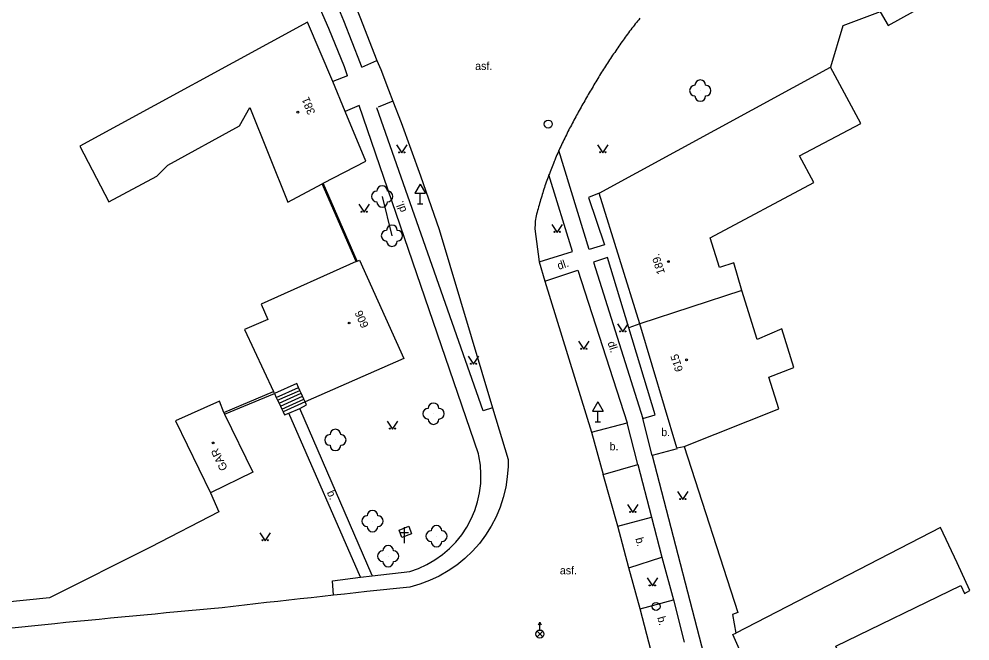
# Model space of a CAD drawing. Extents: x -536391 to -535419, y -1201788 to -1200779.
# Drawn here: x -535590.1 to -535501, y -1201602.5 to -1201544.3 of the extents above; entities that cross this region are included whole.
import ezdxf

# ---------------------------------------------------------------- set-up
doc = ezdxf.new("R2010")
doc.units = 0
for name, color, linetype in [('CIZÍ_NADZEM_POPIS', 7, 'Continuous'), ('CIZÍ_PODZEM', 7, 'Continuous'), ('CIZÍ_PODZEM_POPIS', 7, 'Continuous'), ('ELE_EON', 7, 'Continuous'), ('ELE_EON_POPIS', 7, 'Continuous'), ('KONEC_VEDENÍ', 7, 'Continuous'), ('POL_ZNAČKA_PRACOVNÍ', 7, 'Continuous'), ('SDEL_EON', 7, 'Continuous'), ('SDEL_EON_POPIS', 7, 'Continuous'), ('TECH_OCHR_PÁSMO_HRAN', 7, 'Continuous'), ('ZP_EON', 7, 'Continuous')]:
    doc.layers.add(name, color=color, linetype=linetype)

msp = doc.modelspace()

# ---------------------------------------------------------------- linework, layer by layer
at = {"layer": 'CIZÍ_PODZEM'}
for p, q in [((-535553.96, -1201593.36), (-535553.96, -1201591.86)), ((-535554.335, -1201592.36), (-535553.585, -1201592.36))]:
    msp.add_line(p, q, dxfattribs=at)
for centre in [(-535563.95, -1201552.98), (-535529.23, -1201566.99), (-535559.15, -1201572.74), (-535527.52, -1201576.19), (-535571.89, -1201583.98)]:
    msp.add_circle(centre, 0.0875, dxfattribs=at)
at = {"layer": 'CIZÍ_PODZEM_POPIS'}
for p, q in [((-535552.48, -1201559.724), (-535552.98, -1201560.59)), ((-535552.48, -1201559.724), (-535551.98, -1201560.59)), ((-535552.98, -1201560.59), (-535551.98, -1201560.59)), ((-535552.48, -1201561.59), (-535552.48, -1201560.59)), ((-535552.73, -1201561.59), (-535552.23, -1201561.59)), ((-535535.84, -1201580.134), (-535536.34, -1201581)), ((-535535.84, -1201580.134), (-535535.34, -1201581)), ((-535536.34, -1201581), (-535535.34, -1201581)), ((-535535.84, -1201582), (-535535.84, -1201581)), ((-535536.09, -1201582), (-535535.59, -1201582))]:
    msp.add_line(p, q, dxfattribs=at)
for points in [[(-535509.4, -1201543.6), (-535512.88, -1201544.9), (-535514.03, -1201548.76)], [(-535558.47, -1201566.98), (-535561.66, -1201559.7)], [(-535558.38, -1201566.94), (-535561.57, -1201559.65)], [(-535570.89, -1201581.11), (-535566.22, -1201579.17)], [(-535570.81, -1201581.28), (-535566.14, -1201579.35)], [(-535527.76, -1201584.32), (-535522.72, -1201599.86), (-535523.22, -1201600.05), (-535522.9, -1201601.79)], [(-535572.12, -1201588.65), (-535571.35, -1201590.42), (-535577.76, -1201593.75), (-535587.2, -1201598.48), (-535604.18, -1201600.22)]]:
    msp.add_lwpolyline(points, dxfattribs=at)
at = {"layer": 'ELE_EON'}
for centre, radius in [((-535540.49, -1201554.1), 0.375), ((-535540.49, -1201554.1), 0.0005), ((-535530.38, -1201599.301), 0.375), ((-535530.38, -1201599.301), 0.0005)]:
    msp.add_circle(centre, radius, dxfattribs=at)
at = {"layer": 'ELE_EON_POPIS'}
for p, q in [((-535541.27, -1201601.505), (-535541.27, -1201600.755)), ((-535541.535, -1201602.144), (-535541.006, -1201601.616)), ((-535541.006, -1201602.148), (-535541.535, -1201601.616))]:
    msp.add_line(p, q, dxfattribs=at)
msp.add_lwpolyline([(-535541.395, -1201601.005), (-535541.27, -1201600.755), (-535541.145, -1201601.005)], dxfattribs=at)
msp.add_circle((-535541.27, -1201601.88), 0.375, dxfattribs=at)
at = {"layer": 'KONEC_VEDENÍ'}
msp.add_lwpolyline([(-535556.05, -1201560.88), (-535555.13, -1201564.56)], dxfattribs=at)
for centre in [(-535526.24, -1201550.97), (-535556.05, -1201560.88), (-535555.13, -1201564.56), (-535551.23, -1201581.24), (-535560.43, -1201583.7), (-535556.95, -1201591.3), (-535550.96, -1201592.71), (-535555.48, -1201594.59)]:
    msp.add_circle(centre, 0.0005, dxfattribs=at)
for centre, start, end in [((-535526.24, -1201550.47), 0, 179.99999), ((-535526.74, -1201550.97), 89.99999, 269.99999), ((-535525.74, -1201550.97), 270, 89.99999), ((-535526.24, -1201551.47), 179.99999, 359.99999), ((-535556.05, -1201560.38), 0, 179.99999), ((-535556.55, -1201560.88), 89.99999, 269.99999), ((-535555.55, -1201560.88), 270, 89.99999), ((-535556.05, -1201561.38), 179.99999, 359.99999), ((-535555.13, -1201564.06), 0, 179.99999), ((-535555.63, -1201564.56), 89.99999, 269.99999), ((-535554.63, -1201564.56), 270, 89.99999), ((-535555.13, -1201565.06), 179.99999, 359.99999), ((-535551.73, -1201581.24), 89.99999, 269.99999), ((-535551.23, -1201580.74), 0, 179.99999), ((-535550.73, -1201581.24), 270, 89.99999), ((-535551.23, -1201581.74), 179.99999, 359.99999), ((-535560.93, -1201583.7), 89.99999, 269.99999), ((-535560.43, -1201583.2), 0, 179.99999), ((-535559.93, -1201583.7), 270, 89.99999), ((-535560.43, -1201584.2), 179.99999, 359.99999), ((-535556.95, -1201590.8), 0, 179.99999), ((-535557.45, -1201591.3), 89.99999, 269.99999), ((-535556.45, -1201591.3), 270, 89.99999), ((-535556.95, -1201591.8), 179.99999, 359.99999), ((-535551.46, -1201592.71), 89.99999, 269.99999), ((-535550.96, -1201592.21), 0, 179.99999), ((-535550.46, -1201592.71), 270, 89.99999), ((-535550.96, -1201593.21), 179.99999, 359.99999), ((-535555.98, -1201594.59), 89.99999, 269.99999), ((-535555.48, -1201594.09), 0, 179.99999), ((-535554.98, -1201594.59), 270, 89.99999), ((-535555.48, -1201595.09), 179.99999, 359.99999)]:
    msp.add_arc(centre, 0.5, start, end, dxfattribs=at)
at = {"layer": 'SDEL_EON'}
for points in [[(-535554.71, -1201556.06), (-535554.21, -1201556.81), (-535553.71, -1201556.06)], [(-535535.87, -1201556.04), (-535535.37, -1201556.79), (-535534.87, -1201556.04)], [(-535558.24, -1201561.62), (-535557.74, -1201562.37), (-535557.24, -1201561.62)], [(-535540.15, -1201563.5), (-535539.65, -1201564.25), (-535539.15, -1201563.5)], [(-535534, -1201572.83), (-535533.5, -1201573.58), (-535533, -1201572.83)], [(-535537.65, -1201574.45), (-535537.15, -1201575.2), (-535536.65, -1201574.45)], [(-535547.98, -1201575.86), (-535547.48, -1201576.61), (-535546.98, -1201575.86)], [(-535555.57, -1201581.93), (-535555.07, -1201582.68), (-535554.57, -1201581.93)], [(-535528.37, -1201588.54), (-535527.87, -1201589.29), (-535527.37, -1201588.54)], [(-535533.07, -1201589.74), (-535532.57, -1201590.49), (-535532.07, -1201589.74)], [(-535567.51, -1201592.39), (-535567.01, -1201593.14), (-535566.51, -1201592.39)], [(-535531.23, -1201596.63), (-535530.73, -1201597.38), (-535530.23, -1201596.63)]]:
    msp.add_lwpolyline(points, dxfattribs=at)
for centre in [(-535535.62, -1201556.74), (-535535.12, -1201556.74), (-535554.46, -1201556.76), (-535553.96, -1201556.76), (-535557.99, -1201562.32), (-535557.49, -1201562.32), (-535539.9, -1201564.2), (-535539.4, -1201564.2), (-535533.75, -1201573.53), (-535533.25, -1201573.53), (-535537.4, -1201575.15), (-535536.9, -1201575.15), (-535547.73, -1201576.56), (-535547.23, -1201576.56), (-535555.32, -1201582.63), (-535554.82, -1201582.63), (-535528.12, -1201589.24), (-535527.62, -1201589.24), (-535532.82, -1201590.44), (-535532.32, -1201590.44), (-535567.26, -1201593.09), (-535566.76, -1201593.09), (-535530.98, -1201597.33), (-535530.48, -1201597.33)]:
    msp.add_circle(centre, 0.05, dxfattribs=at)
at = {"layer": 'SDEL_EON_POPIS'}
for points in [[(-535561.57, -1201559.65), (-535557.59, -1201557.59), (-535559.5, -1201552.92), (-535560.67, -1201550.12), (-535563.03, -1201544.54)], [(-535535.71, -1201560.57), (-535514.03, -1201548.76)], [(-535561.66, -1201559.7), (-535561.57, -1201559.65)], [(-535531.9, -1201572.83), (-535535.71, -1201560.57)], [(-535558.38, -1201566.94), (-535558.16, -1201566.84), (-535554.01, -1201576.07), (-535563.27, -1201580.14)], [(-535558.47, -1201566.98), (-535558.38, -1201566.94)], [(-535528.44, -1201584.45), (-535531.9, -1201572.83)], [(-535563.88, -1201578.78), (-535564.05, -1201578.41), (-535566.14, -1201579.35)], [(-535563.76, -1201579.05), (-535563.88, -1201578.78)], [(-535566.14, -1201579.35), (-535566.22, -1201579.17)], [(-535563.64, -1201579.32), (-535563.76, -1201579.05)], [(-535563.51, -1201579.6), (-535563.64, -1201579.32)], [(-535563.39, -1201579.87), (-535563.51, -1201579.6)], [(-535563.27, -1201580.14), (-535563.39, -1201579.87)], [(-535570.81, -1201581.28), (-535568.17, -1201586.7), (-535572.12, -1201588.65)], [(-535570.89, -1201581.11), (-535570.81, -1201581.28)], [(-535528.44, -1201584.45), (-535527.76, -1201584.32)], [(-535523.18, -1201601.94), (-535522.9, -1201601.79)], [(-535516.38, -1201617.2), (-535521.06, -1201606.7), (-535521.43, -1201605.87), (-535523.18, -1201601.94)]]:
    msp.add_lwpolyline(points, dxfattribs=at)
at = {"layer": 'TECH_OCHR_PÁSMO_HRAN'}
for points in [[(-535559.28, -1201549.57), (-535559.59, -1201548.75), (-535561.04, -1201545.16), (-535567.24, -1201530.99), (-535567.78, -1201529.85), (-535568.21, -1201528.88), (-535572, -1201520.91), (-535578.88, -1201508.46), (-535580.82, -1201505.2), (-535588.58, -1201492.55)], [(-535566.65, -1201524.99), (-535563.37, -1201531.99), (-535558.46, -1201543.26), (-535558.14, -1201544.05), (-535556.54, -1201548.16)], [(-535557.96, -1201548.78), (-535558.09, -1201548.43), (-535559.64, -1201544.42), (-535559.94, -1201543.67), (-535565.46, -1201531.02), (-535568.06, -1201525.62)], [(-535531.89, -1201544.19), (-535532, -1201544.32), (-535532.11, -1201544.45), (-535532.22, -1201544.59), (-535532.33, -1201544.72), (-535532.43, -1201544.86), (-535532.54, -1201544.99), (-535532.65, -1201545.13), (-535532.75, -1201545.27), (-535532.86, -1201545.4), (-535532.96, -1201545.54), (-535533.06, -1201545.68), (-535533.17, -1201545.82), (-535533.27, -1201545.96), (-535533.37, -1201546.1), (-535533.47, -1201546.24), (-535533.57, -1201546.38), (-535533.67, -1201546.52), (-535533.77, -1201546.67), (-535533.87, -1201546.81), (-535533.97, -1201546.95), (-535534.07, -1201547.09), (-535534.16, -1201547.23), (-535534.26, -1201547.38), (-535534.36, -1201547.52), (-535534.45, -1201547.66), (-535534.55, -1201547.81), (-535534.65, -1201547.95), (-535534.74, -1201548.09), (-535534.84, -1201548.24), (-535534.93, -1201548.38), (-535535.02, -1201548.53), (-535535.12, -1201548.67), (-535535.21, -1201548.82), (-535535.3, -1201548.96), (-535535.39, -1201549.11), (-535535.49, -1201549.25), (-535535.58, -1201549.4), (-535535.67, -1201549.55), (-535535.76, -1201549.69)], [(-535557.96, -1201548.78), (-535556.54, -1201548.16)], [(-535556.54, -1201548.16), (-535556.17, -1201548.99), (-535555.44, -1201550.89)], [(-535559.28, -1201549.57), (-535560.67, -1201550.12)], [(-535535.76, -1201549.69), (-535535.85, -1201549.84), (-535535.94, -1201549.99), (-535536.03, -1201550.14), (-535536.12, -1201550.28), (-535536.2, -1201550.43), (-535536.29, -1201550.58), (-535536.38, -1201550.73), (-535536.47, -1201550.88), (-535536.56, -1201551.02), (-535536.64, -1201551.17), (-535536.73, -1201551.32), (-535536.82, -1201551.47), (-535536.9, -1201551.62), (-535536.99, -1201551.77), (-535537.07, -1201551.92), (-535537.16, -1201552.07), (-535537.25, -1201552.22), (-535537.33, -1201552.37), (-535537.41, -1201552.52), (-535537.5, -1201552.67), (-535537.58, -1201552.83), (-535537.67, -1201552.98), (-535537.75, -1201553.13), (-535537.83, -1201553.28), (-535537.91, -1201553.43), (-535538, -1201553.58), (-535538.08, -1201553.74), (-535538.16, -1201553.89), (-535538.24, -1201554.04), (-535538.32, -1201554.19), (-535538.4, -1201554.35), (-535538.48, -1201554.5), (-535538.56, -1201554.65), (-535538.64, -1201554.81), (-535538.71, -1201554.96), (-535538.79, -1201555.12), (-535538.87, -1201555.27), (-535538.94, -1201555.42), (-535539.02, -1201555.58), (-535539.09, -1201555.73), (-535539.17, -1201555.89), (-535539.24, -1201556.05), (-535539.31, -1201556.2), (-535539.39, -1201556.36), (-535539.46, -1201556.51), (-535539.49, -1201556.58)], [(-535555.44, -1201550.89), (-535555.04, -1201551.97)], [(-535555.04, -1201551.97), (-535556.43, -1201552.53)], [(-535555.04, -1201551.97), (-535554.27, -1201553.96), (-535552.45, -1201558.95), (-535550.71, -1201563.97), (-535545.7, -1201580.68)], [(-535558.19, -1201552.37), (-535559.5, -1201552.92)], [(-535556.97, -1201596.44), (-535553.45, -1201596.02), (-535552.63, -1201595.73), (-535551.85, -1201595.37), (-535551.1, -1201594.94), (-535550.39, -1201594.44), (-535549.74, -1201593.88), (-535549.13, -1201593.26), (-535548.59, -1201592.58), (-535548.11, -1201591.86), (-535547.7, -1201591.1), (-535547.37, -1201590.31), (-535547.11, -1201589.48), (-535546.92, -1201588.64), (-535546.81, -1201587.78), (-535546.79, -1201586.91), (-535546.84, -1201586.05), (-535546.98, -1201585.2), (-535547.02, -1201584.99), (-535558.19, -1201552.37)], [(-535545.7, -1201580.68), (-535546.57, -1201580.96), (-535556.56, -1201552.58)], [(-535539.49, -1201556.58), (-535539.53, -1201556.67), (-535539.6, -1201556.83), (-535539.67, -1201556.99), (-535539.74, -1201557.15), (-535539.81, -1201557.31), (-535539.87, -1201557.47), (-535539.94, -1201557.62), (-535540, -1201557.78), (-535540.07, -1201557.94), (-535540.13, -1201558.11), (-535540.19, -1201558.26), (-535540.25, -1201558.43), (-535540.31, -1201558.59), (-535540.38, -1201558.75), (-535540.43, -1201558.87)], [(-535536.64, -1201565.86), (-535539.49, -1201556.58)], [(-535540.43, -1201558.87), (-535540.5, -1201559.07), (-535540.56, -1201559.24), (-535540.62, -1201559.4), (-535540.67, -1201559.56), (-535540.73, -1201559.72), (-535540.79, -1201559.89), (-535540.84, -1201560.05), (-535540.89, -1201560.21), (-535540.95, -1201560.38), (-535541, -1201560.54), (-535541.05, -1201560.7), (-535541.1, -1201560.87), (-535541.15, -1201561.03), (-535541.2, -1201561.2), (-535541.25, -1201561.36), (-535541.3, -1201561.53), (-535541.34, -1201561.69), (-535541.39, -1201561.86), (-535541.44, -1201562.03), (-535541.48, -1201562.19), (-535541.53, -1201562.36), (-535541.57, -1201562.53), (-535541.61, -1201562.7), (-535541.66, -1201562.87), (-535541.69, -1201563.04), (-535541.71, -1201563.21), (-535541.72, -1201563.39), (-535541.72, -1201563.56), (-535541.75, -1201563.79), (-535541.73, -1201563.91)], [(-535538.2, -1201566.04), (-535540.43, -1201558.87)], [(-535535.71, -1201560.57), (-535536.7, -1201560.97), (-535535.22, -1201565.41), (-535536.64, -1201565.86)], [(-535541.73, -1201563.91), (-535541.33, -1201567.01)], [(-535541.33, -1201567.01), (-535538.2, -1201566.04)], [(-535541.33, -1201567.01), (-535540.8, -1201568.81)], [(-535532.94, -1201573.19), (-535534.92, -1201566.59), (-535536.26, -1201567.04), (-535531.61, -1201581.69)], [(-535540.8, -1201568.81), (-535537.7, -1201567.79)], [(-535537.7, -1201567.79), (-535533.09, -1201582.08)], [(-535540.8, -1201568.81), (-535536.43, -1201582.96)], [(-535531.9, -1201572.83), (-535532.94, -1201573.19)], [(-535531.61, -1201581.69), (-535530.48, -1201581.33), (-535532.94, -1201573.19)], [(-535565.97, -1201579.71), (-535563.88, -1201578.78)], [(-535566.14, -1201579.35), (-535565.97, -1201579.71)], [(-535565.97, -1201579.71), (-535565.84, -1201579.98)], [(-535565.84, -1201579.98), (-535563.76, -1201579.05)], [(-535565.71, -1201580.25), (-535563.64, -1201579.32)], [(-535565.58, -1201580.52), (-535563.51, -1201579.6)], [(-535565.84, -1201579.98), (-535565.71, -1201580.25)], [(-535565.71, -1201580.25), (-535565.58, -1201580.52)], [(-535565.58, -1201580.52), (-535565.45, -1201580.8)], [(-535565.45, -1201580.8), (-535563.39, -1201579.87)], [(-535563.27, -1201580.14), (-535565.32, -1201581.07)], [(-535565.32, -1201581.07), (-535565.19, -1201581.34), (-535564.79, -1201581.19), (-535563.76, -1201580.74), (-535563.15, -1201580.42), (-535563.27, -1201580.14)], [(-535556.98, -1201596.39), (-535563.76, -1201580.74)], [(-535545.7, -1201580.68), (-535544.25, -1201585.52), (-535544.25, -1201586.18), (-535544.32, -1201587.16), (-535544.47, -1201588.13), (-535544.7, -1201589.08), (-535545, -1201590.01), (-535545.38, -1201590.91), (-535545.83, -1201591.78), (-535546.35, -1201592.61), (-535546.94, -1201593.39), (-535547.59, -1201594.13), (-535548.3, -1201594.8), (-535549.06, -1201595.42), (-535549.86, -1201595.97), (-535550.71, -1201596.46), (-535551.6, -1201596.87), (-535552.52, -1201597.22), (-535553.46, -1201597.48), (-535557.47, -1201597.91), (-535558.52, -1201598.03), (-535559.56, -1201598.14), (-535560.61, -1201598.25)], [(-535565.45, -1201580.8), (-535565.32, -1201581.07)], [(-535558.07, -1201596.56), (-535564.79, -1201581.19)], [(-535536.43, -1201582.96), (-535533.09, -1201582.08)], [(-535532.08, -1201585.99), (-535533.09, -1201582.08)], [(-535530.74, -1201585.15), (-535531.61, -1201581.69)], [(-535536.43, -1201582.96), (-535535.33, -1201586.94)], [(-535528.42, -1201584.52), (-535530.74, -1201585.15)], [(-535530.74, -1201585.15), (-535525.02, -1201607.19), (-535521.43, -1201605.87)], [(-535535.33, -1201586.94), (-535532.08, -1201585.99)], [(-535532.08, -1201585.99), (-535530.82, -1201590.92)], [(-535533.95, -1201591.78), (-535535.33, -1201586.94)], [(-535533.95, -1201591.78), (-535530.82, -1201590.92)], [(-535530.82, -1201590.92), (-535529.85, -1201594.69)], [(-535554.19, -1201592.84), (-535554.46, -1201592.14), (-535553.56, -1201591.78), (-535553.29, -1201592.48), (-535554.19, -1201592.84)], [(-535532.94, -1201595.69), (-535533.95, -1201591.78)], [(-535532.94, -1201595.69), (-535529.85, -1201594.69)], [(-535529.85, -1201594.69), (-535528.76, -1201598.67)], [(-535531.87, -1201599.53), (-535532.94, -1201595.69)], [(-535560.61, -1201598.25), (-535560.69, -1201596.89), (-535558.07, -1201596.56)], [(-535558.07, -1201596.56), (-535556.97, -1201596.44)], [(-535560.61, -1201598.25), (-535561.65, -1201598.37), (-535562.7, -1201598.48), (-535563.74, -1201598.59), (-535564.78, -1201598.7), (-535565.83, -1201598.82), (-535566.87, -1201598.93), (-535567.92, -1201599.06), (-535568.96, -1201599.19), (-535570, -1201599.31), (-535571.05, -1201599.42), (-535572.09, -1201599.51), (-535573.14, -1201599.62), (-535574.18, -1201599.72), (-535575.23, -1201599.81), (-535576.27, -1201599.91), (-535577.32, -1201600.01), (-535578.37, -1201600.11), (-535579.41, -1201600.21), (-535580.46, -1201600.31), (-535581.5, -1201600.41), (-535582.55, -1201600.51), (-535583.59, -1201600.61), (-535584.64, -1201600.71), (-535585.68, -1201600.81), (-535586.73, -1201600.91), (-535601.96, -1201602.45)], [(-535531.87, -1201599.53), (-535528.76, -1201598.67)], [(-535528.76, -1201598.67), (-535527.76, -1201602.65)], [(-535530.83, -1201603.48), (-535531.87, -1201599.53)]]:
    msp.add_lwpolyline(points, dxfattribs=at)
at = {"layer": 'ZP_EON'}
for points in [[(-535509.4, -1201543.6), (-535508.65, -1201544.87), (-535506.27, -1201543.55), (-535509.62, -1201537.58)], [(-535563.03, -1201544.54), (-535584.37, -1201556.16), (-535581.66, -1201561.4), (-535577.17, -1201558.97), (-535576.12, -1201557.94), (-535569.4, -1201554.28), (-535568.45, -1201552.56), (-535564.87, -1201561.42), (-535561.66, -1201559.7)], [(-535522.34, -1201569.68), (-535523.11, -1201567.09), (-535524.44, -1201567.55), (-535525.31, -1201564.75), (-535515.61, -1201559.58), (-535516.95, -1201557.07), (-535511.2, -1201554.06), (-535514.03, -1201548.76)], [(-535558.47, -1201566.98), (-535567.38, -1201570.99), (-535566.75, -1201572.4), (-535568.96, -1201573.36), (-535566.22, -1201579.17)], [(-535527.76, -1201584.32), (-535518.87, -1201580.79), (-535519.83, -1201577.8), (-535517.48, -1201576.9), (-535518.61, -1201573.3), (-535520.9, -1201574.27), (-535522.34, -1201569.68), (-535531.9, -1201572.83)], [(-535570.89, -1201581.11), (-535571.29, -1201580.05), (-535575.42, -1201581.9), (-535572.12, -1201588.65)], [(-535511.42, -1201615.11), (-535512.76, -1201611.86), (-535510.13, -1201610.73), (-535513.53, -1201603.02), (-535501.82, -1201597.33), (-535501.47, -1201598.07), (-535500.97, -1201597.79), (-535502.17, -1201595.2), (-535503.72, -1201591.89), (-535522.9, -1201601.79)]]:
    msp.add_lwpolyline(points, dxfattribs=at)

# ---------------------------------------------------------------- texts
at = {"layer": 'CIZÍ_NADZEM_POPIS'}
for s, rotation, p in [('381', 112.58002, (-535562.29, -1201553.03)), ('189.', 107.40002, (-535529.54, -1201568.05)), ('606', 114.16998, (-535557.28, -1201573)), ('615', 107.27002, (-535527.84, -1201577.18))]:
    msp.add_text(s, height=0.75, rotation=rotation, dxfattribs=at).set_placement(p)
at = {"layer": 'POL_ZNAČKA_PRACOVNÍ'}
for s, p in [('asf.', (-535547.34, -1201549.03)), ('b.', (-535529.9, -1201583.34)), ('b.', (-535534.74, -1201584.67)), ('asf.', (-535539.4, -1201596.29))]:
    msp.add_text(s, height=0.75, dxfattribs=at).set_placement(p)
for s, rotation, p in [('dl.', 109.36, (-535553.75, -1201562.22)), ('dl.', 18.20997, (-535539.5, -1201567.76)), ('dl.', 287.88001, (-535534.94, -1201574.58)), ('GAR', 115.92999, (-535570.5, -1201586.36)), ('b.', 293.62001, (-535561.25, -1201588.61)), ('b.', 284.48002, (-535532.33, -1201592.93)), ('b.', 284.75, (-535530.28, -1201600.33))]:
    msp.add_text(s, height=0.75, rotation=rotation, dxfattribs=at).set_placement(p)

doc.saveas('drawing.dxf')
